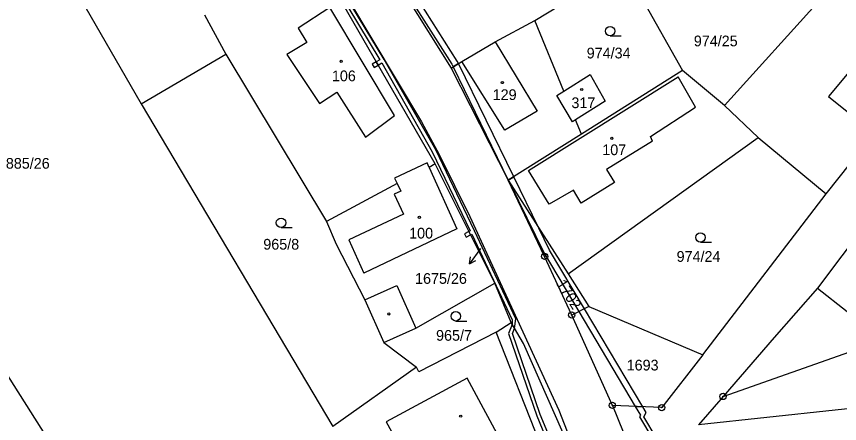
# Model space of a CAD drawing. Extents: x -680203 to -673936, y -1102717 to -1093650.
# Drawn here: x -676925.8 to -676795.2, y -1100824.1 to -1100759.5 of the extents above; entities that cross this region are included whole.
import ezdxf

# ---------------------------------------------------------------- set-up
doc = ezdxf.new("R2010")
doc.units = 0
for name, color, linetype in [('SOxx02xx_Koleje_param další_Popis10', 7, 'Continuous'), ('SOxx02xx_Staničení_Popis10', 7, 'Continuous'), ('SOxxxxxx_Koleje_hlavní_body_Popis10', 7, 'Continuous'), ('SOxxxxxx_Koleje_LN_parametry_Popis10', 7, 'Continuous'), ('SOxxxxxx_Koleje_param další_Popis10', 7, 'Continuous'), ('SOxxxxxx_Osa_bod_P', 7, 'Continuous'), ('SOxxxxxx_Staničení_Popis10', 7, 'Continuous'), ('x_prac', 7, 'Continuous')]:
    doc.layers.add(name, color=color, linetype=linetype)

msp = doc.modelspace()

# ---------------------------------------------------------------- linework, layer by layer
at = {"layer": 'SOxx02xx_Koleje_param další_Popis10'}
for centre, radius in [((-676842.03, -1100797.58), 0.5), ((-676842.03, -1100797.58), 0.0303), ((-676837.72, -1100806.89), 0.5), ((-676837.72, -1100806.89), 0.0303), ((-676813.73, -1100819.81), 0.5), ((-676831.27, -1100821.23), 0.5), ((-676813.73, -1100819.81), 0.0303), ((-676831.27, -1100821.23), 0.0303), ((-676823.45, -1100821.58), 0.5), ((-676823.45, -1100821.58), 0.0303)]:
    msp.add_circle(centre, radius, dxfattribs=at)
at = {"layer": 'SOxx02xx_Staničení_Popis10'}
for p, q in [((-676852.18, -1100796.33), (-676853.94, -1100798.76)), ((-676853.94, -1100798.76), (-676853.76, -1100797.65)), ((-676853.94, -1100798.76), (-676852.95, -1100798.24))]:
    msp.add_line(p, q, dxfattribs=at)
at = {"layer": 'SOxxxxxx_Koleje_hlavní_body_Popis10'}
for p, q in [((-676831.64, -1100762.59), (-676829.89, -1100762.59)), ((-676883.83, -1100793), (-676882.08, -1100793)), ((-676817.31, -1100795.32), (-676815.56, -1100795.32)), ((-676856.11, -1100807.84), (-676854.36, -1100807.84))]:
    msp.add_line(p, q, dxfattribs=at)
for centre in [(-676831.64, -1100761.84), (-676883.83, -1100792.25), (-676817.31, -1100794.57), (-676856.11, -1100807.09)]:
    msp.add_circle(centre, 0.75, dxfattribs=at)
at = {"layer": 'SOxxxxxx_Koleje_LN_parametry_Popis10'}
for points in [[(-676866.86, -1100751.14), (-676856.75, -1100767.08), (-676856.53, -1100767.53), (-676855.68, -1100767), (-676855.87, -1100766.6), (-676865.96, -1100750.68)], [(-676869.07, -1100767.6), (-676868.43, -1100767.22), (-676868.73, -1100766.7), (-676869.37, -1100767.08)], [(-676856.53, -1100767.53), (-676847.78, -1100785.48), (-676846.92, -1100784.94), (-676855.68, -1100767)], [(-676841.24, -1100796.59), (-676842.94, -1100793.1), (-676846.92, -1100784.94), (-676847.78, -1100785.48), (-676847.54, -1100785.96), (-676842.12, -1100797.07), (-676836.6, -1100806.34), (-676827.64, -1100821.39), (-676826.44, -1100821.45), (-676835.7, -1100805.9)], [(-676854.73, -1100793.98), (-676854.46, -1100794.52), (-676853.77, -1100794.17), (-676854.04, -1100793.63)]]:
    msp.add_lwpolyline(points, close=True, dxfattribs=at)
for points in [[(-676874.94, -1100755.13), (-676868.16, -1100766.37), (-676868.73, -1100766.7), (-676868.43, -1100767.22), (-676867.86, -1100766.89), (-676859.84, -1100780.97), (-676853.84, -1100793.53), (-676854.04, -1100793.63), (-676853.77, -1100794.17), (-676853.58, -1100794.07), (-676847.19, -1100807.65), (-676847.16, -1100808.4), (-676847.75, -1100809.8), (-676843.28, -1100822.91), (-676840.73, -1100829.06)], [(-676840.06, -1100829.13), (-676842.72, -1100822.69), (-676847.11, -1100809.82), (-676846.78, -1100809.04), (-676846.59, -1100807.51), (-676853.17, -1100793.53), (-676859.3, -1100780.69), (-676867.49, -1100766.33), (-676874.56, -1100754.61)], [(-676822.35, -1100829.62), (-676826.27, -1100823.02), (-676825.9, -1100822.36), (-676826.44, -1100821.45), (-676827.64, -1100821.39), (-676826.82, -1100822.76), (-676826.97, -1100823.02), (-676822.76, -1100830.11)]]:
    msp.add_lwpolyline(points, dxfattribs=at)
at = {"layer": 'SOxxxxxx_Koleje_param další_Popis10'}
for centre in [(-676874.29, -1100766.62), (-676848.72, -1100770), (-676836.14, -1100771.1), (-676831.37, -1100778.84), (-676861.89, -1100791.38), (-676866.73, -1100806.71), (-676855.33, -1100822.94)]:
    msp.add_circle(centre, 0.175, dxfattribs=at)
at = {"layer": 'SOxxxxxx_Staničení_Popis10'}
for p, q in [((-676876.1, -1100758.11), (-676881.12, -1100761.38)), ((-676865.85, -1100775.22), (-676876.1, -1100758.11)), ((-676786.47, -1100759.55), (-676796.99, -1100772.21)), ((-676881.12, -1100761.38), (-676879.72, -1100763.63)), ((-676879.72, -1100763.63), (-676882.92, -1100765.55)), ((-676849.87, -1100763.54), (-676843.2, -1100774.56)), ((-676882.92, -1100765.55), (-676877.71, -1100773.32)), ((-676848.35, -1100777.54), (-676855.13, -1100766.66)), ((-676844.6, -1100783.95), (-676820.86, -1100769.08)), ((-676818.11, -1100773.9), (-676820.86, -1100769.08)), ((-676877.71, -1100773.32), (-676874.98, -1100771.52)), ((-676874.98, -1100771.52), (-676870.44, -1100778.65)), ((-676796.99, -1100772.21), (-676789.75, -1100778.06)), ((-676843.2, -1100774.56), (-676848.35, -1100777.54)), ((-676825.25, -1100778.57), (-676818.11, -1100773.9)), ((-676870.44, -1100778.65), (-676865.85, -1100775.22)), ((-676824.92, -1100779.32), (-676825.25, -1100778.57)), ((-676824.92, -1100779.32), (-676832.21, -1100783.79)), ((-676860.35, -1100783.46), (-676855.97, -1100793.19)), ((-676841.29, -1100789.29), (-676844.6, -1100783.95)), ((-676832.21, -1100783.79), (-676830.94, -1100785.87)), ((-676865.39, -1100786), (-676864.81, -1100787.22)), ((-676830.94, -1100785.87), (-676836.25, -1100789.15)), ((-676864.81, -1100787.22), (-676865.88, -1100787.72)), ((-676865.88, -1100787.72), (-676864.42, -1100790.9)), ((-676837.44, -1100787.07), (-676841.29, -1100789.29)), ((-676836.25, -1100789.15), (-676837.44, -1100787.07)), ((-676864.42, -1100790.9), (-676873.08, -1100794.94)), ((-676855.97, -1100793.19), (-676870.7, -1100800.23)), ((-676873.08, -1100794.94), (-676870.7, -1100800.23)), ((-676870.56, -1100804.5), (-676865.48, -1100802.19)), ((-676865.48, -1100802.19), (-676862.44, -1100808.97)), ((-676798.77, -1100802.64), (-676794.04, -1100806.34))]:
    msp.add_line(p, q, dxfattribs=at)
at = {"layer": 'x_prac'}
for p, q in [((-676930.99, -1100729.9), (-676906, -1100773.4)), ((-676859.39, -1100782.92), (-676878.93, -1100748.98)), ((-676867.1, -1100751.27), (-676856.87, -1100767.74)), ((-676829.43, -1100751.52), (-676820.13, -1100768.1)), ((-676843.56, -1100760.13), (-676830.08, -1100751.93)), ((-676795.08, -1100753.24), (-676813.48, -1100773.66)), ((-676895.94, -1100759.26), (-676892.59, -1100765.49)), ((-676838.99, -1100771.34), (-676843.56, -1100760.13)), ((-676906, -1100773.4), (-676892.59, -1100765.49)), ((-676892.59, -1100765.49), (-676876.64, -1100792.04)), ((-676856.87, -1100767.74), (-676847.83, -1100785.51)), ((-676820.13, -1100768.1), (-676836.19, -1100778.19)), ((-676813.48, -1100773.66), (-676820.13, -1100768.1)), ((-676838.99, -1100771.34), (-676834.79, -1100768.73)), ((-676834.79, -1100768.73), (-676832.44, -1100772.95)), ((-676840.1, -1100772.03), (-676838.99, -1100771.34)), ((-676837.62, -1100776.22), (-676840.1, -1100772.03)), ((-676906, -1100773.4), (-676875.62, -1100824.57)), ((-676832.44, -1100772.95), (-676837.12, -1100775.9)), ((-676808.14, -1100778.74), (-676813.48, -1100773.66)), ((-676837.12, -1100775.9), (-676837.62, -1100776.22)), ((-676836.19, -1100778.19), (-676837.12, -1100775.9)), ((-676836.19, -1100778.19), (-676847.83, -1100785.51)), ((-676838.28, -1100800.34), (-676808.14, -1100778.74)), ((-676808.14, -1100778.74), (-676797.35, -1100787.64)), ((-676849.94, -1100801.83), (-676859.39, -1100782.92)), ((-676847.83, -1100785.51), (-676838.28, -1100800.34)), ((-676816.95, -1100813.21), (-676797.35, -1100787.64)), ((-676876.64, -1100792.04), (-676875.06, -1100795.64)), ((-676838.28, -1100800.34), (-676835.02, -1100805.56)), ((-676862.44, -1100808.97), (-676849.94, -1100801.83)), ((-676847.35, -1100808.07), (-676849.94, -1100801.83)), ((-676835.02, -1100805.56), (-676837.72, -1100806.89)), ((-676835.02, -1100805.56), (-676816.95, -1100813.21)), ((-676831.27, -1100821.23), (-676837.72, -1100806.89)), ((-676867.5, -1100811.26), (-676862.44, -1100808.97)), ((-676849.72, -1100809.59), (-676847.35, -1100808.07)), ((-676841.34, -1100830.79), (-676849.72, -1100809.59)), ((-676867.5, -1100811.26), (-676862.36, -1100815.17)), ((-676862.36, -1100815.17), (-676875.62, -1100824.57)), ((-676813.73, -1100819.81), (-676817.64, -1100824.3))]:
    msp.add_line(p, q, dxfattribs=at)
for points in [[(-676996.19, -1100686.18), (-676938.85, -1100798.17), (-676871.57, -1100904.42), (-676865.84, -1100914.75)], [(-676889.38, -1100729.75), (-676888.9, -1100730.46), (-676861.55, -1100776.21), (-676858.77, -1100781.44), (-676853.86, -1100791.28), (-676839.77, -1100821.96), (-676837.21, -1100828.48)], [(-676856.87, -1100767.74), (-676855.13, -1100766.66), (-676849.87, -1100763.54), (-676843.56, -1100760.13)], [(-676797.35, -1100787.64), (-676789.75, -1100778.06), (-676779.69, -1100765.2)], [(-676859.39, -1100782.92), (-676860.35, -1100783.46), (-676860.65, -1100782.74), (-676865.81, -1100785.16), (-676865.39, -1100786), (-676876.64, -1100792.04)], [(-676837.72, -1100806.89), (-676842.03, -1100797.58), (-676847.83, -1100785.51)], [(-676787, -1100787.02), (-676798.77, -1100802.64), (-676805.62, -1100810.46), (-676813.73, -1100819.81)], [(-676875.06, -1100795.64), (-676870.56, -1100804.5), (-676867.5, -1100811.26)], [(-676813.73, -1100819.81), (-676791.84, -1100812.1), (-676771.7, -1100798.48)], [(-676837.88, -1100828.38), (-676845.38, -1100811.42), (-676847.35, -1100808.07)], [(-676849.72, -1100809.59), (-676861.98, -1100815.88), (-676862.36, -1100815.17)], [(-676816.95, -1100813.21), (-676823.45, -1100821.58), (-676831.27, -1100821.23)], [(-676848.05, -1100828.49), (-676854.29, -1100816.9), (-676867.16, -1100823.83), (-676864.3, -1100829), (-676859.77, -1100826.55), (-676856.36, -1100832.82), (-676848.05, -1100828.49)], [(-676730.8, -1100870.87), (-676736.06, -1100854.01), (-676742.65, -1100840.34), (-676736.87, -1100837.45), (-676738.04, -1100834.98), (-676744.06, -1100837.76), (-676746.8, -1100833.39), (-676749.81, -1100829.32), (-676752.86, -1100826.51), (-676760.89, -1100822.22), (-676768.22, -1100820.45), (-676774.95, -1100820.06), (-676785.11, -1100820.83), (-676817.64, -1100824.3)], [(-676831.27, -1100821.23), (-676826.06, -1100834.06), (-676824.73, -1100832.47)]]:
    msp.add_lwpolyline(points, dxfattribs=at)

# ---------------------------------------------------------------- texts
at = {"layer": 'SOxxxxxx_Osa_bod_P'}
for s, p in [('974/25', (-676818.36, -1100764.25)), ('974/34', (-676835.35, -1100766.17)), ('106', (-676875.76, -1100769.79)), ('129', (-676850.26, -1100772.77)), ('317', (-676837.77, -1100774.06)), ('107', (-676832.88, -1100781.52)), ('885/26', (-676927.47, -1100783.67)), ('100', (-676863.51, -1100794.75)), ('965/8', (-676886.64, -1100796.51)), ('974/24', (-676821.09, -1100798.45)), ('1675/26', (-676862.57, -1100801.94)), ('965/7', (-676859.24, -1100810.97)), ('1693', (-676829.01, -1100815.69))]:
    msp.add_text(s, height=1.7, dxfattribs=at).set_placement(p)
msp.add_text('1702', height=1.7, rotation=303, dxfattribs=at).set_placement((-676840.25, -1100801.94))

doc.saveas('drawing.dxf')
